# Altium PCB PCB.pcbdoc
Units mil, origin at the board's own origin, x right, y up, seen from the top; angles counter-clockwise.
Board outline 2007.87 x 1102.36 mil, 2 copper layers (Top Layer, Bottom Layer); 14 components, 14 nets, 39 pads, 8 vias.
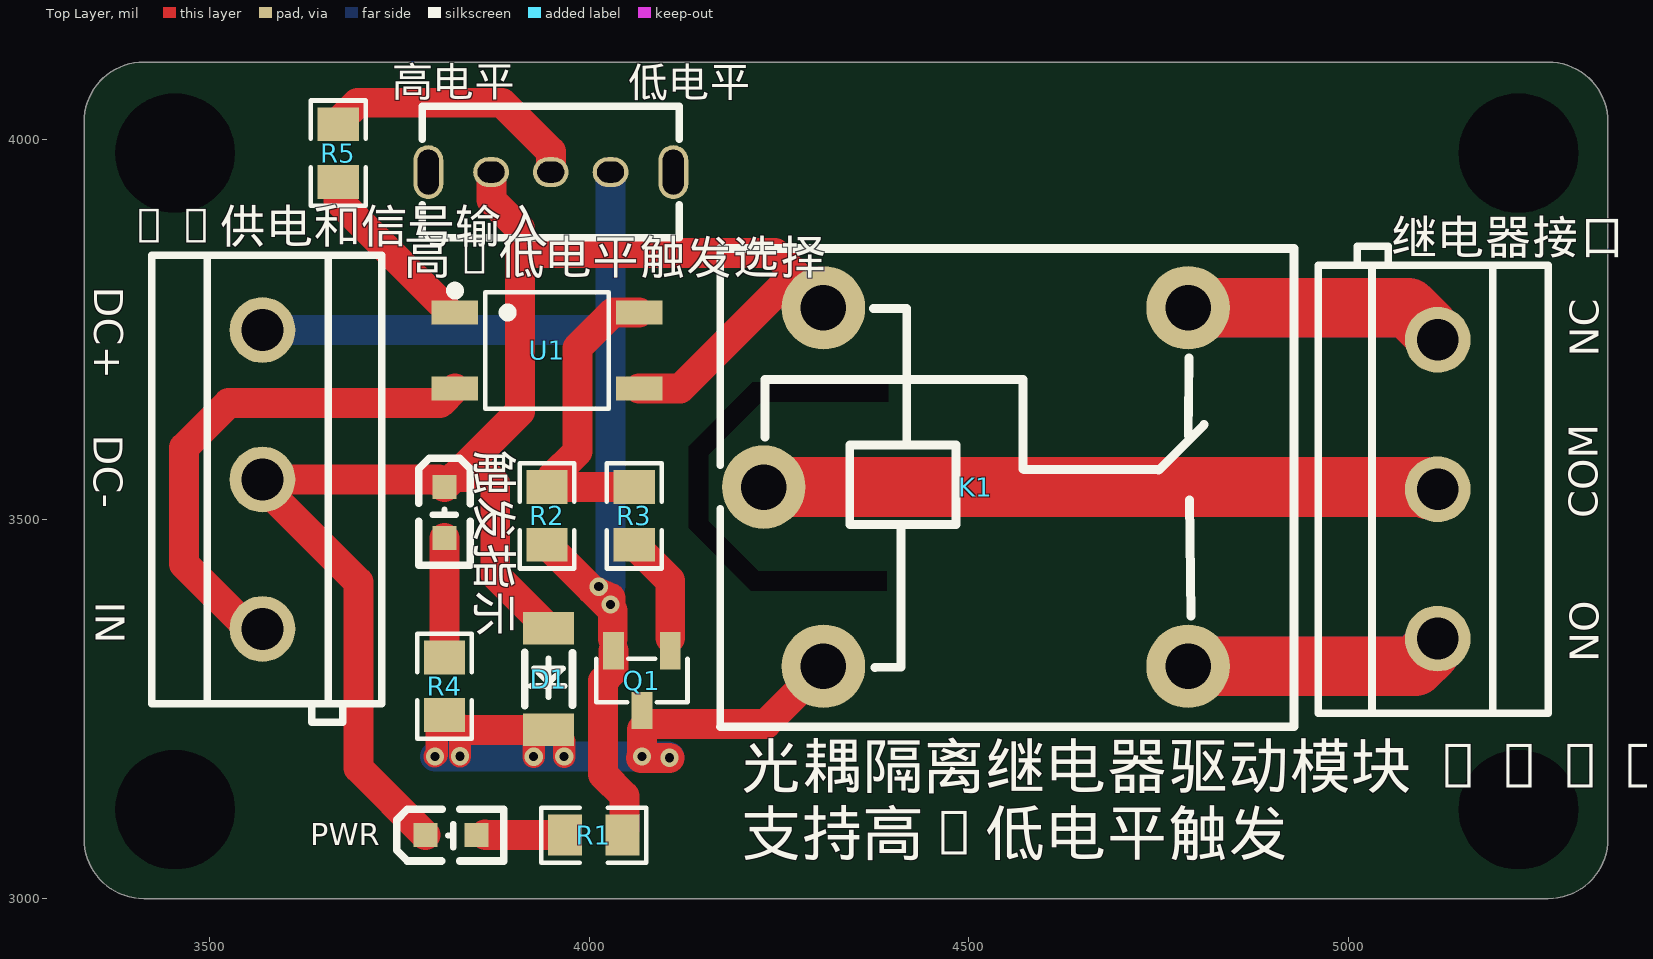
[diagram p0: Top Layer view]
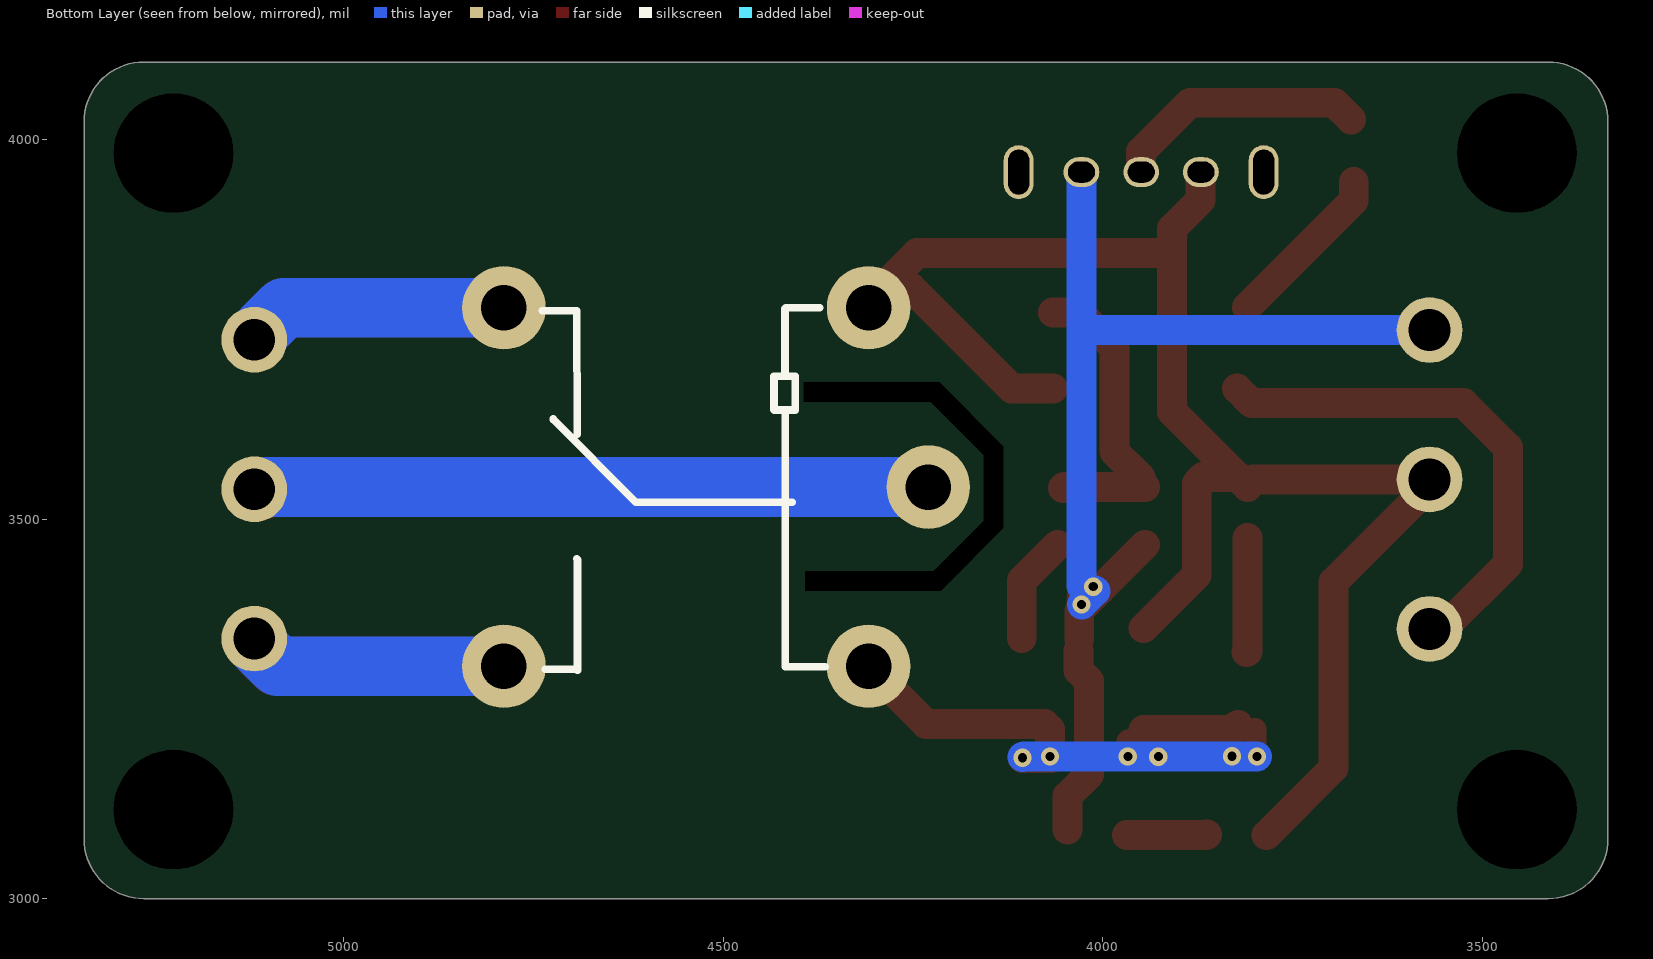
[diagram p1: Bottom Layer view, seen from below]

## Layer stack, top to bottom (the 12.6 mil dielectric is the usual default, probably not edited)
Top Solder: solder mask 0.4, Solder Resist, Dk 3.5
Top Layer: signal copper 1.4
Dielectric 1: dielectric 12.6, FR-4, Dk 4.8
Bottom Layer: signal copper 1.4
Bottom Solder: solder mask 0.4, Solder Resist, Dk 3.5

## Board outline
3413.34,3000 5263.73,3000 ccw(c5263.73,3078.74) 5342.47,3078.74 5342.47,4023.62 ccw(c5263.73,4023.62) 5263.73,4102.36 3413.34,4102.36 ccw(c3413.34,4023.62) 3334.6,4023.62 3334.6,3078.74 ccw(c3413.34,3078.74)
cut-out: 3533.34,3982.36 ccw(c3454.6,3982.36) 3375.86,3982.36 ccw(c3454.6,3982.36)
cut-out: 3533.34,3117.36 ccw(c3454.6,3117.36) 3375.86,3117.36 ccw(c3454.6,3117.36)
cut-out: 5303.34,3117.36 ccw(c5224.6,3117.36) 5145.86,3117.36 ccw(c5224.6,3117.36)
cut-out: 5303.34,3982.36 ccw(c5224.6,3982.36) 5145.86,3982.36 ccw(c5224.6,3982.36)
cut-out: 4212.89,3405.95 4392.18,3405.95 4392.18,3431.3 4212.89,3431.3
cut-out: 4215.09,3655.05 4394.38,3655.05 4394.38,3680.41 4215.09,3680.41
cut-out: 4215.12,3680.38 4131.04,3596.3 4131.04,3487.77 4212.85,3405.96 4215.34,3405.96 4236.4,3405.96 4242.63,3412.19 4157.15,3497.67 4157.15,3584.32 4253.24,3680.4 4215.15,3680.4

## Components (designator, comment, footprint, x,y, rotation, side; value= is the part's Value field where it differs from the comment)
5V供电和信号输入 "" CONN-TH_3P-P5.00_KF301-5.0-3P 3569.6,3552.36 r270 top
D1 "" LL-34_L3.5-W1.5-RD 3946.67,3289.43 r90 top
K1 "" RELAY-TH_HF3FF-XX-1ZXX-XXX 4509.6,3542.36 r0 top
PWR "" LED0603-R-RD 3818.1,3083.7 r0 top
Q1 "" SOT-23-3_L2.9-W1.3-P1.90-LS2.4-BR 4069.6,3287.36 r90 top
R1 "" R0805 4006.16,3083.73 r0 top
R2 "" R0805 3944.6,3504.36 r90 top
R3 "" R0805 4059.6,3504.36 r90 top
R4 "" R0805 3809.6,3279.95 r90 top
R5 "" R0805 3669.6,3982.36 r90 top
U1 "" SOP-4_L3.9-W4.4-P2.54-LS7.0-TL 3944.6,3722.36 r0 top
继电器接口 "" CONN-TH_3P-P5.00_KF301-5.0-3P 5118.2,3539.46 r90 top
触发指示 "" LED0603-R-RD 3809.6,3508.86 r270 top
高/低电平触发选择 "" SW-TH_SK-12D02VG3 3949.6,3957.36 r180 top

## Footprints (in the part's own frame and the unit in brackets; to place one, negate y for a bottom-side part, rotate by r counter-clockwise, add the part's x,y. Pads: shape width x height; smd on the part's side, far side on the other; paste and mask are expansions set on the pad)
CONN-TH_3P-P5.00_KF301-5.0-3P [mil]
  round 86.6 hole 55.1: 1(-196.8,0) 2(0,0) 3(196.9,0)
  silkscreen extent -295,-146 320,158
LED0603-R-RD [mm]
  rect 0.8x0.8 smd: 1(0.851,0) 2(-0.851,0)
  silkscreen extent -1.82,-0.86 1.77,0.86
LL-34_L3.5-W1.5-RD [mil]
  rect 43.3x66.9 smd: 1(-66.9,0) 2(66.9,0)
  silkscreen extent -35,-32 35,32
R0805 [mil]
  rect 44.6x54.2 smd: 1(-38,0) 2(38,0)
  silkscreen extent -69,-36 69,36
RELAY-TH_HF3FF-XX-1ZXX-XXX [mil]
  round 110 hole 60: 1(-200.8,236.2) 2(-200.8,-236.2) 3(279.6,-236.2) 4(-279.5,0) 5(279.6,236.2)
  silkscreen extent -337,-316 419,314
SOP-4_L3.9-W4.4-P2.54-LS7.0-TL [mil]
  rect 61.4x31.5 smd: 1(-121.3,50) 2(-121.3,-50) 3(121.3,-50) 4(121.3,50)
  silkscreen extent -127,-77 82,85
SOT-23-3_L2.9-W1.3-P1.90-LS2.4-BR [mil]
  rect 49.2x27.6 smd: 1(39.4,-37.4) 2(39.4,37.4) 3(-39.4,0)
  silkscreen extent -29,-60 29,60
SW-TH_SK-12D02VG3 [mil]
  oval 47.2x39.4 hole 27.6 slot 35.4 at 0 deg: 1(-78.7,0) 2(0,0) 3(78.7,0)
  oval 39.4x70.9 hole 27.6 slot 59.1 at 90 deg: 4(161.4,0) 5(-161.4,0)
  silkscreen extent -169,-87 169,87

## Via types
v1: diameter 24.02, hole 12.01, Top Layer to Bottom Layer, 8 vias

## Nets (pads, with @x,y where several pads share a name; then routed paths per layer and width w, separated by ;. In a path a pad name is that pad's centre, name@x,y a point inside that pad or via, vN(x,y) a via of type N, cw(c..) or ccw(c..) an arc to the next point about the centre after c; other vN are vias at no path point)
$1N492: PWR.1 R1.1 | length 105.9
  Top Layer w39.4: PWR.1@3862.73,3084.81 3863.81,3083.73 R1.1
$1N935: R2.2 R3.2 U1.4 | length 395.7
  Top Layer w39.4: R2.2 4051.38,3542.36 R3.2@4052.87,3540.88 ; R2.2@3949.69,3553.87 3984.84,3589.03 3984.84,3725.84 4031.37,3772.36 U1.4
$1N939: Q1.1 R3.1 | length 142.5
  Top Layer w39.4: R3.1 4106.94,3419.02 Q1.1@4106.94,3343.5
$1N1058: R4.2 触发指示.1 | length 151
  Top Layer w39.4: 触发指示.1 3809.6,3325.89 R4.2@3810.69,3324.8
$1N1359: R5.1 U1.1 | length 223.8
  Top Layer w39.4: R5.1 3669.6,3919.9 U1.1@3810.52,3778.98
$1N1760: D1.1 K1.2 Q1.3 R4.1 | length 894.1
  Top Layer w29.5: v1(3796.87,3187.35) 3799.12,3189.6 R4.1@3799.12,3223.42 ; R4.1@3826.98,3227.5 3829.99,3224.48 3829.99,3222.53 v1(3829.99,3187.64) ; D1.1@3926.68,3207.96 3927.04,3207.6 v1(3927.04,3187.11) ; D1.1@3966.93,3207.96 3967.19,3207.7 v1(3967.19,3187.19)
  Top Layer w39.4: R4.1@3822.22,3229.2 3828.89,3222.53 3829.99,3222.53 D1.1 ; v1@4068.35,3185.53 4105.83,3185.53 v1(4106.05,3185.76) ; v1(4069.71,3187.42) 4069.71,3223.17 Q1.3@4070.09,3223.55 ; Q1.3@4076.62,3230.37 4233.01,3230.37 K1.2
  Bottom Layer w39.4: v1(3796.87,3187.35) 4069.71,3187.35 4104.91,3187.35 v1@4105.77,3186.48
$1N3387: K1.4 继电器接口.2 | length 1765.2
  Top Layer w78.7: K1.4 5102.74,3542.36 继电器接口.2@5106.37,3538.73
  Bottom Layer w78.7: K1.4 5112.34,3542.36 继电器接口.2@5116.03,3538.67
$1N5124: K1.3 继电器接口.1 | length 665.4
  Top Layer w78.7: K1.3 5088.19,3306.16 继电器接口.1@5108.09,3326.06
  Bottom Layer w78.7: K1.3 5087.21,3306.16 继电器接口.1@5115.65,3334.6
$1N5141: K1.5 继电器接口.3 | length 661
  Top Layer w78.7: K1.5 5079.2,3778.56 继电器接口.3@5108.09,3749.68
  Bottom Layer w78.7: K1.5 5079.25,3778.56 继电器接口.3@5107.63,3750.19
DC+: 5V供电和信号输入.1 Q1.2 R1.2 R2.1 高/低电平触发选择.1 | length 1499.6
  Top Layer w39.4: R2.1 v1@4003.48,3407.48 ; v1(4028.07,3387.51) 4028.07,3396.11 v1@4003.48,3407.48 ; Q1.2@4031.27,3341.97 4031.27,3379.69 v1@4003.48,3407.48 ; Q1.2 4032.2,3300.77 4018.58,3287.15 4018.58,3163.47 4046.73,3135.31 R1.2@4046.73,3090.99
  Bottom Layer w10: v1@4012.02,3409.48 4012.75,3410.21 v1(4012.75,3411.16)
  Bottom Layer w39.4: 5V供电和信号输入.1 4025.86,3749.16 4027.18,3750.49 ; v1@4027.75,3387.41 4027.96,3387.62 4009.99,3405.6 4028.3,3412.03 高/低电平触发选择.1
DC-: 5V供电和信号输入.2 D1.2 K1.1 PWR.2 U1.3 触发指示.2 高/低电平触发选择.3 | length 2220.8
  Top Layer w39.4: 5V供电和信号输入.2 5V供电和信号输入.2@3576.88,3552.36 ; PWR.2 3696.11,3172.19 3696.11,3417.09 3578.03,3535.17 5V供电和信号输入.2@3576.88,3552.36 ; 触发指示.2@3805.68,3549.1 3802.41,3552.36 5V供电和信号输入.2@3576.88,3552.36 ; 触发指示.2 触发指示.2@3823.04,3555.8 ; 触发指示.2@3821.39,3555.8 触发指示.2@3823.04,3555.8 ; 高/低电平触发选择.3@3871.22,3948.19 3871.22,3920.67 3908.86,3883.03 3908.86,3850.61 ; D1.2 3876.42,3426.58 3876.42,3547.4 3868.02,3555.8 触发指示.2@3823.04,3555.8 ; U1.3 4120.15,3672.36 4253.11,3805.33 K1.1@4274.89,3805.33 ; K1.1@4306.99,3788.7 4245.09,3850.61 3908.86,3850.61 ; 触发指示.2@3823.04,3555.8 3908.86,3641.62 3908.86,3850.61
IN: 5V供电和信号输入.3 U1.2 | length 660.5
  Top Layer w39.4: 5V供电和信号输入.3@3549.85,3357.47 3466.54,3440.78 3466.54,3594.4 3525.01,3652.87 3803.81,3652.87 U1.2
NET4: R5.2 高/低电平触发选择.2 | length 339.7
  Top Layer w39.4: R5.2@3672.95,4026.61 3695.11,4048.78 3885.42,4048.78 3949.6,3984.6 高/低电平触发选择.2
"": 高/低电平触发选择.4 高/低电平触发选择.5

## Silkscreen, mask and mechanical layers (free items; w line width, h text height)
Top Overlay:
  text "高电平" at 3740.54,4057.58 h39.66
  text "低电平" at 4050.94,4056.72 h39.66
  text "DC+" at 3348.21,3806.53 h38.33 r270
  text "NC" at 5330.57,3713.88 h38.33 r90
  text "DC-" at 3347.26,3611.35 h38.33 r270
  text "COM" at 5329.11,3501.5 h38.33 r90
  text "IN" at 3349.99,3391.04 h38.33 r270
  text "NO" at 5330.44,3311.48 h38.33 r90
  text "光耦隔离继电器驱动模块 (5V) / 支持高/低电平触发" at 4199.61,3057.92 h58.86
Bottom Overlay:
  lines w10 net "": 4365.83,3305.83 4418.83,3305.83 4418.51,3306.15 4418.51,3639.45 ; 4373.1,3778.48 4417.93,3778.48 4418.86,3777.55 4418.86,3690.3 4419.4,3689.77 ; 4409.18,3522.51 4615.54,3522.51 4616.68,3523.66 4724.45,3631.42 4724.45,3632.57 ; 4692.35,3301.25 4692.35,3446.85 4693.49,3447.99 ; 4692.86,3302.39 4693.05,3302.2 4734.89,3302.2 ; 4692.86,3632 4692.65,3612.32 4693.05,3774.76 4693.18,3774.63 4738.91,3774.63 ; 4405.39,3643.91 4405.39,3688.24 4433.41,3688.24 4433.41,3644.42 4432.9,3643.91 4405.39,3643.91
Mechanical 1:
  circle w1 net "": c3454.6,3982.36 r78.74
  circle w1 net "": c3454.6,3117.36 r78.74
  circle w1 net "": c5224.6,3117.36 r78.74
  circle w1 net "": c5224.6,3982.36 r78.74
  lines w1 net "": 4215.09,3680.41 4394.38,3680.41 4394.38,3655.05 4215.09,3655.05 4215.09,3680.41 ; 4215.12,3680.38 4131.04,3596.3 4131.04,3487.77 4212.85,3405.96 4215.34,3405.96 4236.4,3405.96 4242.63,3412.19 4157.15,3497.67 4157.15,3584.32 4253.24,3680.4 4215.15,3680.4 4215.12,3680.38 ; 4212.89,3405.95 4392.18,3405.95 4392.18,3431.3 4212.89,3431.3 4212.89,3405.95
